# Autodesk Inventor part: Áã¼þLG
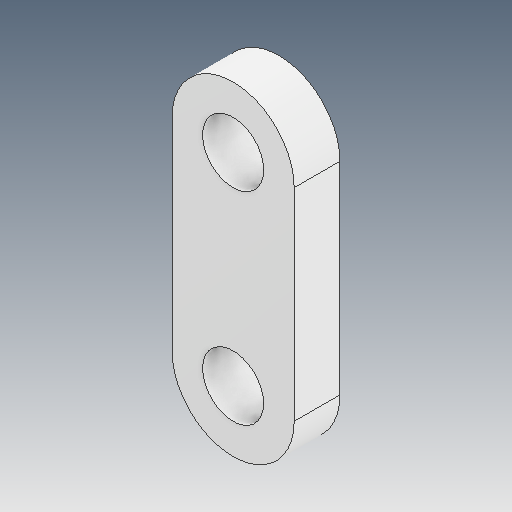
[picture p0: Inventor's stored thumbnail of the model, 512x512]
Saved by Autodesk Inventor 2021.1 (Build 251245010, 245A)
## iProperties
Created: 2021-05
Part Number: Áã¼þLG
Material: Ogólny
Document SubType Name: Modeling
Designer: user
Density: 1 g/cm^3
Appearance: Domyślna
Author: user
Revision Number: ÈÎºÎ
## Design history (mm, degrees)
feature "ÊäÈë1"
node "Bryła1"
